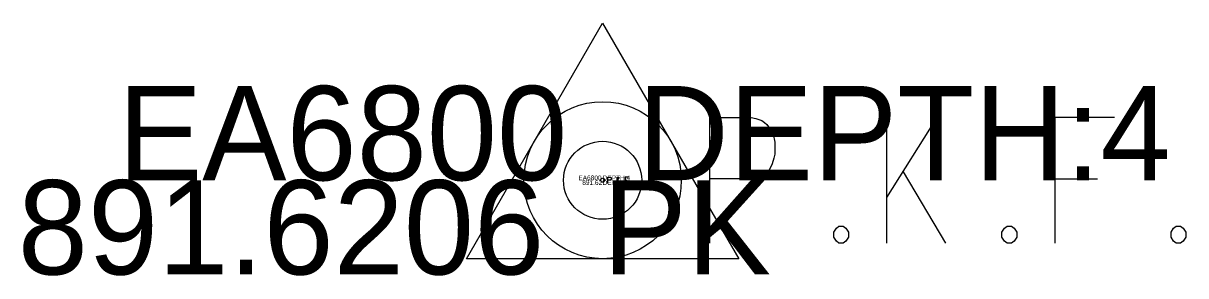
# Model space of a CAD drawing. Extents: x 179044 to 189691, y 286531 to 301257.
# Drawn here: x 181669.7 to 181684.47, y 300611.57 to 300614.78 of the extents above; entities that cross this region are included whole.
import ezdxf

# ---------------------------------------------------------------- set-up
doc = ezdxf.new("R2010")
doc.units = 0
for name, color, linetype in [('SV_Control_Point', 7, 'Continuous'), ('SV_X_Control_Cells_Found', 7, 'Continuous'), ('SV_X_Text_Comment', 7, 'Continuous'), ('SV_X_Text_Description', 7, 'Continuous'), ('SV_X_Text_Elevation', 7, 'Continuous'), ('SV_X_Text_Name', 7, 'Continuous')]:
    doc.layers.add(name, color=color, linetype=linetype)

msp = doc.modelspace()

# ---------------------------------------------------------------- linework, layer by layer
at = {"layer": 'SV_Control_Point'}
for p, q in [((181675.33, 300611.785), (181677.062, 300614.785)), ((181677.062, 300614.785), (181678.794, 300611.785)), ((181677.062, 300612.785), (181677.062, 300612.785)), ((181678.794, 300611.785), (181675.33, 300611.785))]:
    msp.add_line(p, q, dxfattribs=at)
msp.add_circle((181677.062, 300612.785), 1, dxfattribs=at)
at = {"layer": 'SV_X_Control_Cells_Found'}
for points in [[(181678.423, 300611.984), (181678.423, 300613.584), (181678.952, 300613.584), (181679.008, 300613.572), (181679.085, 300613.546), (181679.118, 300613.521), (181679.151, 300613.496), (181679.195, 300613.433), (181679.228, 300613.37), (181679.25, 300613.269), (181679.25, 300613.118), (181679.239, 300613.068), (181679.217, 300612.992), (181679.173, 300612.904), (181679.129, 300612.866), (181679.096, 300612.841), (181679.041, 300612.816), (181678.952, 300612.803), (181678.423, 300612.803)], [(181680.672, 300613.584), (181680.672, 300611.984)], [(181681.311, 300613.584), (181680.672, 300612.564)], [(181683.571, 300613.584), (181682.811, 300613.584), (181682.811, 300611.984)], [(181680.882, 300612.891), (181681.422, 300611.984)], [(181677.13, 300612.745), (181677.13, 300612.825), (181677.157, 300612.825), (181677.159, 300612.824), (181677.163, 300612.823), (181677.165, 300612.822), (181677.166, 300612.82), (181677.169, 300612.817), (181677.17, 300612.814), (181677.171, 300612.809), (181677.171, 300612.801), (181677.171, 300612.799), (181677.17, 300612.795), (181677.168, 300612.791), (181677.165, 300612.789), (181677.164, 300612.788), (181677.161, 300612.786), (181677.157, 300612.786), (181677.13, 300612.786)], [(181677.212, 300612.755), (181677.215, 300612.755), (181677.217, 300612.754), (181677.218, 300612.752), (181677.218, 300612.749), (181677.217, 300612.746), (181677.215, 300612.745), (181677.212, 300612.745), (181677.211, 300612.746), (181677.209, 300612.749), (181677.209, 300612.752), (181677.211, 300612.754), (181677.212, 300612.755)], [(181677.243, 300612.825), (181677.243, 300612.745)], [(181677.274, 300612.825), (181677.243, 300612.774)], [(181677.253, 300612.79), (181677.28, 300612.745)], [(181677.319, 300612.755), (181677.322, 300612.755), (181677.324, 300612.754), (181677.325, 300612.752), (181677.325, 300612.749), (181677.324, 300612.746), (181677.322, 300612.745), (181677.319, 300612.745), (181677.317, 300612.746), (181677.316, 300612.749), (181677.316, 300612.752), (181677.317, 300612.754), (181677.319, 300612.755)], [(181677.387, 300612.825), (181677.349, 300612.825), (181677.349, 300612.745)], [(181677.349, 300612.786), (181677.376, 300612.786)], [(181677.427, 300612.755), (181677.429, 300612.755), (181677.431, 300612.754), (181677.433, 300612.752), (181677.433, 300612.749), (181677.431, 300612.746), (181677.429, 300612.745), (181677.427, 300612.745), (181677.425, 300612.746), (181677.423, 300612.749), (181677.423, 300612.752), (181677.425, 300612.754), (181677.427, 300612.755)], [(181682.811, 300612.803), (181683.351, 300612.803)], [(181680.066, 300612.198), (181680.121, 300612.198), (181680.154, 300612.173), (181680.187, 300612.123), (181680.187, 300612.06), (181680.154, 300612.009), (181680.121, 300611.984), (181680.066, 300611.984), (181680.033, 300612.009), (181680, 300612.06), (181680, 300612.123), (181680.033, 300612.173), (181680.066, 300612.198)], [(181682.204, 300612.198), (181682.259, 300612.198), (181682.293, 300612.173), (181682.326, 300612.123), (181682.326, 300612.06), (181682.293, 300612.009), (181682.259, 300611.984), (181682.204, 300611.984), (181682.171, 300612.009), (181682.138, 300612.06), (181682.138, 300612.123), (181682.171, 300612.173), (181682.204, 300612.198)], [(181684.354, 300612.198), (181684.409, 300612.198), (181684.442, 300612.173), (181684.475, 300612.123), (181684.475, 300612.06), (181684.442, 300612.009), (181684.409, 300611.984), (181684.354, 300611.984), (181684.321, 300612.009), (181684.288, 300612.06), (181684.288, 300612.123), (181684.321, 300612.173), (181684.354, 300612.198)]]:
    msp.add_lwpolyline(points, dxfattribs=at)
for centre, radius in [((181677.062, 300612.784), 0.497), ((181677.062, 300612.785), 0.0249)]:
    msp.add_circle(centre, radius, dxfattribs=at)

# ---------------------------------------------------------------- texts
at = {"layer": 'SV_X_Text_Comment'}
for s, height, p in [('DEPTH=4', 0.06, (181677.062, 300612.725)), ('PK', 1.2, (181677.062, 300611.585))]:
    msp.add_text(s, height=height, dxfattribs=at).set_placement(p)
at = {"layer": 'SV_X_Text_Description'}
for s, height in [(' DEPTH:4', 1.2), ('DEPTH:4', 0.06)]:
    msp.add_text(s, height=height, dxfattribs=at).set_placement((181677.062, 300612.785))
at = {"layer": 'SV_X_Text_Elevation'}
for s, height, p in [('891.6206', 1.2, (181669.627, 300611.585)), ('891.62', 0.06, (181676.803, 300612.725))]:
    msp.add_text(s, height=height, dxfattribs=at).set_placement(p)
at = {"layer": 'SV_X_Text_Name'}
for height, p in [(1.2, (181670.902, 300612.785)), (0.06, (181676.754, 300612.785))]:
    msp.add_text('EA6800', height=height, dxfattribs=at).set_placement(p)

doc.saveas('drawing.dxf')
